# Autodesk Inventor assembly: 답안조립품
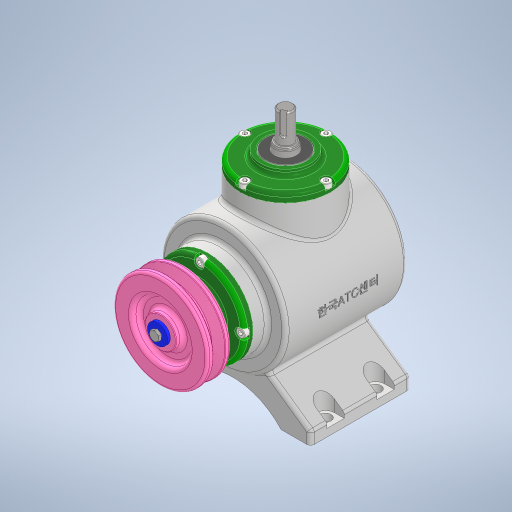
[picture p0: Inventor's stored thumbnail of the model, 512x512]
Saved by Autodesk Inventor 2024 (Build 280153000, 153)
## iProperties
Created: 2023-08
Part Number: 답안조립품
Document SubType Name: Assembly
Designer: Owner
Author: Owner
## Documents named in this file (17)
- C:\Users\Owner\Desktop\730813V1012\답안조립품.iam
- C:\Users\Owner\Desktop\730813V1012\본체.ipt
- C:\Users\Owner\Desktop\730813V1012\V-벨트풀리.ipt
- C:\Users\Owner\Desktop\730813V1012\메인 베벨기어.ipt
- C:\Users\Owner\Desktop\730813V1012\메인 축.ipt
- 메인 축.ipt
- C:\Users\Owner\Desktop\730813V1012\베어링 6203.ipt
- C:\Users\Owner\Desktop\730813V1012\볼트 M4 x 10.ipt
- C:\Users\Owner\Desktop\730813V1012\서브 베벨기어.ipt
- C:\Users\Owner\Desktop\730813V1012\서브 축.ipt
- 서브 축.ipt
- C:\Users\Owner\Desktop\730813V1012\오일실 17 x 32 x 8.ipt
- C:\Users\Owner\Desktop\730813V1012\와셔 4 x 16.ipt
- C:\Users\Owner\Desktop\730813V1012\육각볼트 M4 x 8.ipt
- C:\Users\Owner\Desktop\730813V1012\커버.ipt
- C:\Users\Owner\Desktop\730813V1012\키 4 x 4 x 14.ipt
- C:\Users\Owner\Desktop\730813V1012\키 5 x 5 x 14.ipt
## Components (1 placed, 1 different names)
1. V-벨트풀리:1
